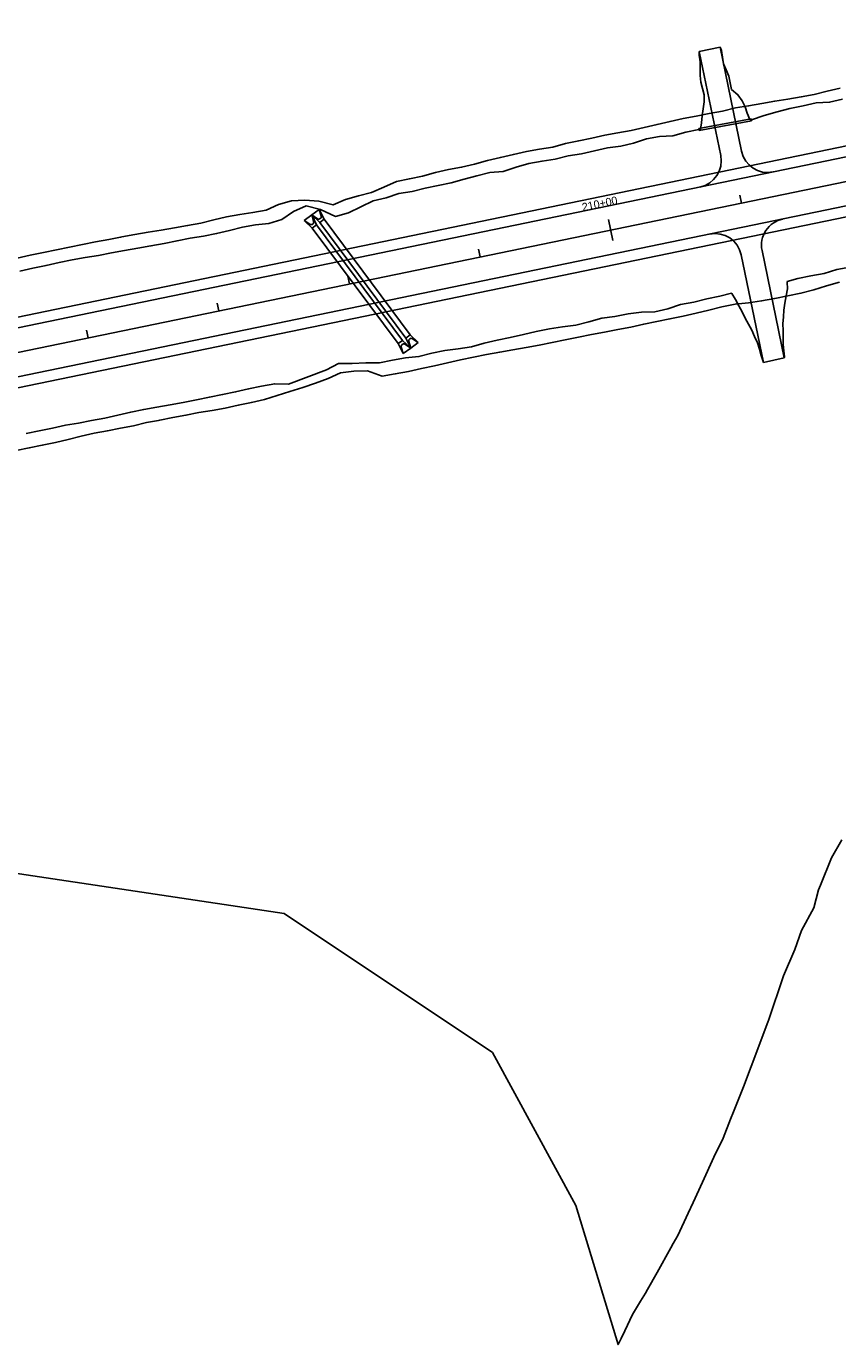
# Model space of a CAD drawing. Extents: x 979959 to 994833, y 1835619 to 1845316.
# Drawn here: x 986328 to 986936, y 1837381 to 1838370 of the extents above; entities that cross this region are included whole.
import ezdxf

# ---------------------------------------------------------------- set-up
doc = ezdxf.new("R2010")
doc.units = 0
for name, color, linetype in [('43', 7, 'Continuous'), ('Future 5 Lane Construction Limits', 7, 'Continuous'), ('R_Drainage', 7, 'Continuous'), ('R_Horz Alg', 7, 'Continuous'), ('R_Horz Alg Stationing', 7, 'Continuous'), ('R_Proposed Const Limits', 7, 'Continuous'), ('R_Proposed Road', 7, 'Continuous')]:
    doc.layers.add(name, color=color, linetype=linetype)

msp = doc.modelspace()

# ---------------------------------------------------------------- linework, layer by layer
at = {"layer": '43'}
msp.add_lwpolyline([(986313.23, 1837735.71), (986521.54, 1837704.48), (986677.83, 1837600.28), (986740.32, 1837485.71), (986771.96, 1837381.29), (986774.24, 1837385.9), (986776.94, 1837391.61), (986782.6, 1837404), (986788.69, 1837413.82), (986792.36, 1837419.94), (986794.06, 1837422.67), (986801.15, 1837435.41), (986811.39, 1837453.91), (986813.31, 1837457.18), (986816.62, 1837463.07), (986824.56, 1837479.94), (986828.3, 1837487.9), (986835.26, 1837503.2), (986843.78, 1837521.9), (986850.58, 1837536.17), (986856.2, 1837550.26), (986858.34, 1837555.85), (986865.8, 1837574.63), (986871.69, 1837589.88), (986875.24, 1837599.18), (986884.38, 1837623.85), (986884.59, 1837624.28), (986896.01, 1837657.84), (986904.34, 1837677.58), (986909.41, 1837691.8), (986918.57, 1837708.79), (986922.11, 1837722.23), (986923.77, 1837725.82), (986932.01, 1837746.29), (986939.76, 1837759.75)], dxfattribs=at)
at = {"layer": 'Future 5 Lane Construction Limits'}
for points in [[(986321.46, 1838195.91), (986331.22, 1838198.09), (986341.02, 1838200.07), (986350.82, 1838202.05), (986360.62, 1838204.04), (986370.4, 1838206.16), (986380.23, 1838207.99), (986390.06, 1838209.82), (986398.98, 1838211.54), (986399.88, 1838211.72), (986409.71, 1838213.59), (986419.56, 1838215.33), (986429.44, 1838216.94), (986439.31, 1838218.58), (986449.18, 1838220.22), (986459.01, 1838222.08), (986468.72, 1838224.5), (986478.45, 1838226.82), (986488.3, 1838228.57), (986498.18, 1838230.19), (986508.07, 1838231.75), (986517.4, 1838235.99), (986527.05, 1838238.73), (986537.12, 1838239.38), (986547.52, 1838238.5), (986558.28, 1838235.82), (986567.66, 1838239.87), (986577.33, 1838242.49), (986587, 1838245.11), (986596.37, 1838249.16), (986605.7, 1838253.43), (986615.5, 1838255.41), (986625.32, 1838257.31), (986634.98, 1838259.97), (986644.73, 1838262.2), (986654.58, 1838263.99), (986664.32, 1838266.25), (986673.95, 1838269.08), (986683.69, 1838271.34), (986693.44, 1838273.6), (986703.21, 1838275.7), (986713.03, 1838277.61), (986722.92, 1838279.18), (986732.59, 1838281.8), (986742.38, 1838283.82), (986752.19, 1838285.77), (986761.95, 1838287.94), (986771.76, 1838289.9), (986781.63, 1838291.52), (986791.38, 1838293.79), (986801.11, 1838296.08), (986810.85, 1838298.37), (986820.63, 1838300.47), (986830.44, 1838302.4), (986840.24, 1838304.38), (986850.11, 1838306.06), (986859.83, 1838308.44), (986869.71, 1838310.01), (986879.57, 1838311.71), (986889.4, 1838313.59), (986899.28, 1838315.16), (986909.18, 1838316.68), (986918.99, 1838318.63), (986928.69, 1838321.1), (986938.42, 1838323.42)], [(986320.62, 1838051.59), (986330.42, 1838053.58), (986340.22, 1838055.58), (986350.01, 1838057.62), (986359.73, 1838059.98), (986369.45, 1838062.38), (986379.21, 1838064.58), (986389.02, 1838066.49), (986398.85, 1838068.36), (986408.67, 1838070.25), (986418.38, 1838072.67), (986427.32, 1838074.25), (986428.23, 1838074.43), (986438.05, 1838076.3), (986447.89, 1838078.08), (986457.7, 1838080.05), (986467.56, 1838081.75), (986477.41, 1838083.49), (986487.19, 1838085.59), (986496.95, 1838087.75), (986506.72, 1838089.91), (986516.33, 1838092.79), (986525.91, 1838095.87), (986535.48, 1838098.98), (986545.05, 1838102.08), (986554.53, 1838105.62), (986563.88, 1838109.79), (986573.83, 1838111.05), (986583.96, 1838111.42), (986595.03, 1838107.28), (986604.86, 1838109.1), (986614.68, 1838110.99), (986624.47, 1838113.05), (986634.24, 1838115.19), (986644, 1838117.37), (986653.75, 1838119.58), (986663.52, 1838121.74), (986673.34, 1838123.64), (986683.17, 1838125.47), (986693.03, 1838127.18), (986702.89, 1838128.89), (986712.73, 1838130.66), (986722.54, 1838132.62), (986732.34, 1838134.59), (986742.15, 1838136.55), (986751.96, 1838138.51), (986761.77, 1838140.43), (986771.59, 1838142.3), (986781.42, 1838144.18), (986791.16, 1838146.43), (986800.95, 1838148.48), (986810.78, 1838150.35), (986820.59, 1838152.26), (986830.32, 1838154.59), (986840.05, 1838156.92), (986849.78, 1838159.25), (986859.58, 1838161.25), (986869.58, 1838162.28), (986879.47, 1838163.84), (986889.29, 1838165.71), (986899.12, 1838167.58), (986908.92, 1838169.55), (986918.59, 1838172.17), (986928.17, 1838175.22), (986937.85, 1838177.8)]]:
    msp.add_lwpolyline(points, dxfattribs=at)
at = {"layer": 'R_Drainage'}
for p, q in [((986832.39, 1838293.14), (986871.73, 1838300.37)), ((986832.66, 1838291.67), (986872, 1838298.89)), ((986872, 1838298.89), (986871.73, 1838300.37)), ((986832.66, 1838291.67), (986832.39, 1838293.14)), ((986536.58, 1838224.05), (986542.2, 1838228.23)), ((986542.2, 1838228.23), (986547.81, 1838232.41)), ((986545.87, 1838220.78), (986542.2, 1838228.23)), ((986543.64, 1838223.31), (986542.2, 1838228.23)), ((986548.28, 1838222.57), (986542.2, 1838228.23)), ((986546.5, 1838225.43), (986542.2, 1838228.23)), ((986551.49, 1838224.96), (986547.81, 1838232.41)), ((986549.26, 1838227.49), (986547.81, 1838232.41)), ((986542.66, 1838218.39), (986536.58, 1838224.05)), ((986540.88, 1838221.25), (986536.58, 1838224.05)), ((986542.66, 1838218.39), (986545.87, 1838220.78)), ((986542.66, 1838218.39), (986607.15, 1838131.76)), ((986545.87, 1838220.78), (986610.36, 1838134.15)), ((986548.28, 1838222.57), (986551.49, 1838224.96)), ((986548.28, 1838222.57), (986612.77, 1838135.94)), ((986551.49, 1838224.96), (986615.98, 1838138.33)), ((986612.77, 1838135.94), (986615.98, 1838138.33)), ((986615.98, 1838138.33), (986622.06, 1838132.67)), ((986607.15, 1838131.76), (986610.36, 1838134.15)), ((986607.15, 1838131.76), (986610.83, 1838124.31)), ((986609.38, 1838129.23), (986610.83, 1838124.31)), ((986610.36, 1838134.15), (986616.44, 1838128.49)), ((986610.83, 1838124.31), (986616.44, 1838128.49)), ((986612.14, 1838131.28), (986616.44, 1838128.49)), ((986612.77, 1838135.94), (986616.44, 1838128.49)), ((986615, 1838133.41), (986616.44, 1838128.49)), ((986616.44, 1838128.49), (986622.06, 1838132.67)), ((986617.76, 1838135.46), (986622.06, 1838132.67))]:
    msp.add_line(p, q, dxfattribs=at)
for centre, start, end in [((986547.49, 1838226.97), 236.98304, 16.34588), ((986541.88, 1838222.79), 236.98304, 16.34588), ((986611.15, 1838129.74), 56.98287, 196.34572), ((986616.76, 1838133.92), 56.98287, 196.34572)]:
    msp.add_arc(centre, 1.83, start, end, dxfattribs=at)
at = {"layer": 'R_Horz Alg'}
msp.add_line((984572.47, 1837764.03), (990033.82, 1838891.48), dxfattribs=at)
at = {"layer": 'R_Horz Alg Stationing'}
for points in [[(986863.12, 1838243.04), (986864.33, 1838237.17)], [(986764.78, 1838224.78), (986768.01, 1838209.11)], [(986667.25, 1838202.61), (986668.46, 1838196.73)], [(986569.31, 1838182.39), (986570.53, 1838176.51)], [(986471.38, 1838162.17), (986472.59, 1838156.29)], [(986373.44, 1838141.95), (986374.66, 1838136.08)]]:
    msp.add_lwpolyline(points, dxfattribs=at)
at = {"layer": 'R_Proposed Const Limits'}
msp.add_line((986553.2, 1838112.06), (986524.78, 1838101.33), dxfattribs=at)
for points in [[(986833.66, 1838292.59), (986834.42, 1838297.36), (986834.98, 1838302.58), (986835.79, 1838307.86), (986836.5, 1838313.11), (986836.44, 1838318.2), (986835.21, 1838323.05), (986833.84, 1838327.87), (986833.35, 1838332.88), (986833.39, 1838337.99), (986833.52, 1838343.13), (986832.8, 1838348.08), (986832.69, 1838350.87)], [(986870.9, 1838299.52), (986870.76, 1838299.76), (986868.76, 1838304.45), (986867.06, 1838309.21), (986864.93, 1838313.87), (986861.78, 1838318.33), (986856.85, 1838322.41), (986855.82, 1838327.31), (986855.04, 1838332.25), (986852.92, 1838336.92), (986851.05, 1838341.64), (986850.22, 1838346.57), (986849.4, 1838351.51), (986848.38, 1838354)], [(986870.9, 1838299.52), (986871.88, 1838299.51), (986881.44, 1838302.69), (986891.08, 1838305.43), (986900.77, 1838307.97), (986910.57, 1838309.94), (986920.31, 1838312.21), (986930.42, 1838312.73), (986940.16, 1838314.98)], [(986323.48, 1838186.12), (986333.25, 1838188.27), (986343.02, 1838190.39), (986352.8, 1838192.48), (986362.58, 1838194.57), (986372.4, 1838196.44), (986382.31, 1838197.94), (986392.12, 1838199.85), (986401.97, 1838201.59), (986411.83, 1838203.3), (986421.68, 1838205.05), (986431.52, 1838206.84), (986441.31, 1838208.89), (986451.11, 1838210.88), (986461, 1838212.46), (986470.83, 1838214.27), (986480.56, 1838216.62), (986490.27, 1838219.05), (986500.13, 1838220.75), (986510.1, 1838221.92), (986519.69, 1838224.9), (986528.66, 1838230.92), (986537.99, 1838235.2), (986548.81, 1838232.22), (986560.07, 1838227.15), (986569.75, 1838229.71), (986579, 1838234.4), (986588.31, 1838238.73), (986598.03, 1838241.1), (986607.59, 1838244.26), (986617.46, 1838245.92), (986627.19, 1838248.27), (986636.98, 1838250.27), (986646.77, 1838252.35), (986656.44, 1838254.98), (986666.1, 1838257.62), (986675.83, 1838259.95), (986685.85, 1838260.87), (986695.38, 1838264.17), (986705.06, 1838266.73), (986714.89, 1838268.58), (986724.79, 1838270.11), (986734.52, 1838272.45), (986744.37, 1838274.17), (986754.15, 1838276.29), (986763.9, 1838278.49), (986773.84, 1838279.79), (986783.57, 1838282.14), (986793.13, 1838285.28), (986802.97, 1838287.11), (986813.06, 1838287.66), (986822.73, 1838290.29), (986832.51, 1838292.37), (986833.66, 1838292.59)], [(986898.62, 1838178.23), (986906.65, 1838180.55), (986916.42, 1838182.68), (986926.28, 1838184.4), (986935.88, 1838187.34), (986945.73, 1838189.08)], [(986898.62, 1838178.23), (986898.55, 1838177.86), (986898.99, 1838172.85), (986897.95, 1838167.52), (986896.93, 1838162.21), (986896.2, 1838156.95), (986895.84, 1838151.77), (986895.52, 1838146.6), (986895.74, 1838141.54), (986895.66, 1838136.42), (986895.75, 1838131.33), (986896.06, 1838126.29), (986896.54, 1838121.89), (986896.48, 1838121.01)], [(986553.2, 1838112.06), (986562.4, 1838116.96), (986572.63, 1838116.87), (986582.75, 1838117.3), (986592.95, 1838117.33), (986602.76, 1838119.31), (986612.6, 1838121.07), (986622.62, 1838122.02), (986632.32, 1838124.5), (986642.07, 1838126.74), (986652.05, 1838127.86), (986661.95, 1838129.33), (986671.59, 1838132.11), (986681.32, 1838134.42), (986691.11, 1838136.49), (986700.88, 1838138.63), (986710.6, 1838140.97), (986720.43, 1838142.85), (986730.35, 1838144.26), (986740.25, 1838145.73), (986749.99, 1838148.03), (986759.64, 1838150.77), (986769.57, 1838152.12), (986779.38, 1838154.04), (986789.33, 1838155.31), (986799.46, 1838155.69), (986809.23, 1838157.85), (986818.78, 1838161.05), (986828.6, 1838162.92), (986838.33, 1838165.26), (986848.1, 1838167.42), (986856.91, 1838169.59)], [(986856.91, 1838169.59), (986857.11, 1838169.3), (986859.85, 1838164.76), (986862.48, 1838160.2), (986864.97, 1838155.61), (986867.1, 1838150.95), (986869.58, 1838146.35), (986872.19, 1838141.79), (986874.09, 1838137.07), (986876.44, 1838132.45), (986877.97, 1838127.67), (986879.28, 1838122.82), (986880.85, 1838117.59)], [(986328.19, 1838064.39), (986337.99, 1838066.4), (986347.78, 1838068.43), (986357.56, 1838070.52), (986367.42, 1838072.19), (986377.24, 1838074.08), (986387.07, 1838075.94), (986396.84, 1838078.1), (986406.57, 1838080.42), (986416.35, 1838082.51), (986426.21, 1838084.19), (986436.09, 1838085.79), (986445.92, 1838087.65), (986455.72, 1838089.65), (986465.51, 1838091.69), (986475.33, 1838093.54), (986485.13, 1838095.57), (986494.89, 1838097.76), (986504.64, 1838099.97), (986514.49, 1838101.72), (986524.78, 1838101.33)]]:
    msp.add_lwpolyline(points, dxfattribs=at)
at = {"layer": 'R_Proposed Road'}
for p, q in [((984567.22, 1837789.49), (990028.56, 1838916.94)), ((984568.84, 1837781.66), (990030.18, 1838909.11)), ((984576.11, 1837746.4), (990037.46, 1838873.85)), ((984577.73, 1837738.57), (990039.08, 1838866.02)), ((986832.69, 1838350.87), (986848.38, 1838354)), ((986832.69, 1838350.87), (986848.81, 1838272.76)), ((986848.38, 1838354), (986864.48, 1838276)), ((986880.85, 1838117.59), (986864.18, 1838198.33)), ((986896.48, 1838121.01), (986879.85, 1838201.57)), ((986880.85, 1838117.59), (986896.48, 1838121.01))]:
    msp.add_line(p, q, dxfattribs=at)
for centre, start, end in [((986884.07, 1838280.04), 191.66438, 281.66438), ((986829.23, 1838268.72), 281.66438, 11.66438), ((986899.43, 1838205.61), 101.66438, 191.66438), ((986844.59, 1838194.29), 11.66438, 101.66438)]:
    msp.add_arc(centre, 20, start, end, dxfattribs=at)

# ---------------------------------------------------------------- texts
at = {"layer": 'R_Horz Alg Stationing'}
msp.add_text('210+00', height=6, rotation=11.66438, dxfattribs=at).set_placement((986745.48, 1838231.01))

doc.saveas('drawing.dxf')
